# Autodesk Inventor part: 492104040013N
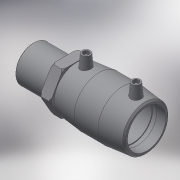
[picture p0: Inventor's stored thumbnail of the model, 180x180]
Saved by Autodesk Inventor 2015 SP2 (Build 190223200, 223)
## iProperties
Created: 2017-06
Part Number: 492104040013N
Material: Generic
Description: PLASSON Male Transition Coupler 40 x 11⁄4"
Document SubType Name: Modeling
Designer: KIM
Mass: 171.687 g
Surface Area: 497.049 cm^2
Volume: 171.687 cm^3
Density: 1 g/cm^3
Appearance: Default
Author: KIM
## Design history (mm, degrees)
derived "492104.ipt"
feature "Solid1::492104.ipt"
tag "TaggingFeature1"
body "Solid1"
other parameters: "d0" = 98, "d2" = 56, "d3" = 48, "d4" = 32.66667, "d5" = 50.4, "d6" = 38, "d8" = 168 deg, "d10" = 19.2, "d11" = 6.4, "d29" = 46, "d30" = 14, "d31" = 34.3, "d34" = 5 deg, "d41" = 4, "d42" = 14, "d43" = 0, "d48" = 3, "d49" = 0, "d58" = 41.91, "d59" = 33.528, "d60" = 49.5, "d61" = 56, "d62" = 0.8382, "d65" = 1.68, "d70" = 0.1, "d71" = 55, "d72" = 13.75, "d73" = 19.2, "d75" = 0, "L_" = 153, "L_1" = 48, "D_1" = 56, "A_" = 46, "d_2" = 12, "L_2" = 55, "R_" = 41.91
